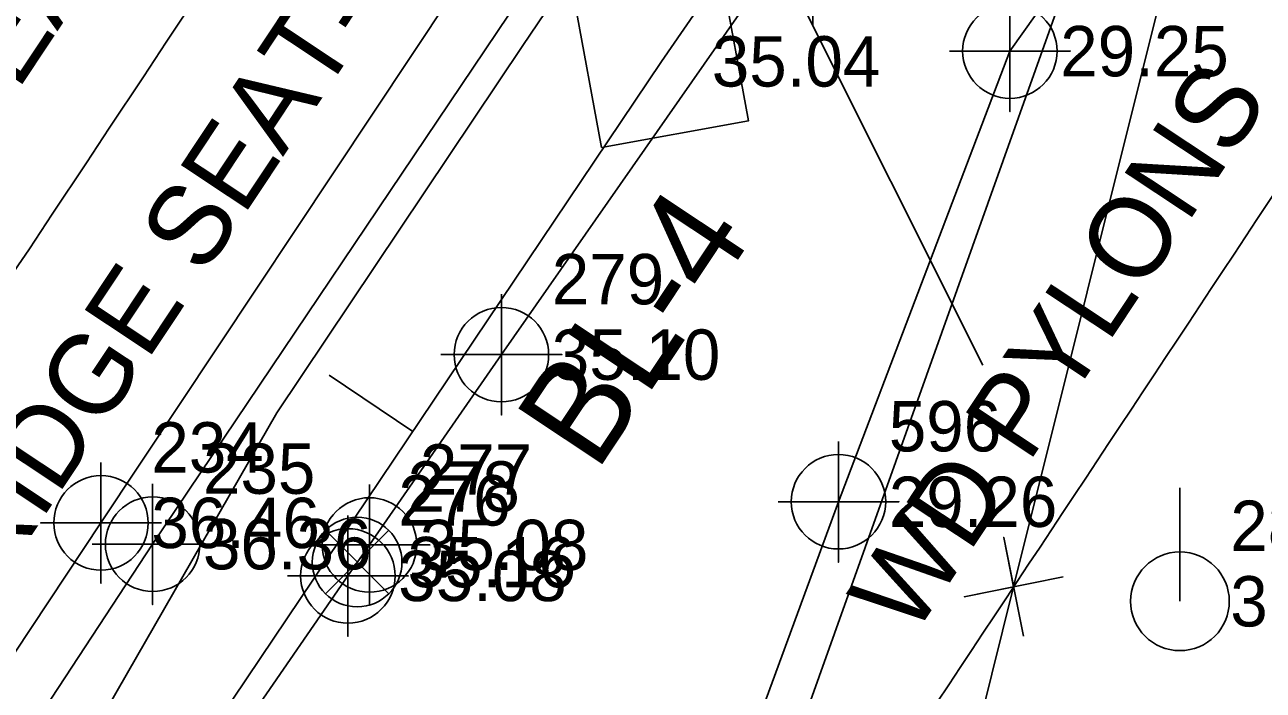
# Model space of a CAD drawing. Extents: x 2603627 to 2605187, y 896619 to 899063.
# Drawn here: x 2604513.4 to 2604574.8, y 898093.2 to 898126.3 of the extents above; entities that cross this region are included whole.
import ezdxf

# ---------------------------------------------------------------- set-up
doc = ezdxf.new("R2010")
doc.units = 0
for name, color, linetype in [('CTL Supplemental Horizontal and Vertical CELL', 7, 'Continuous'), ('CTL Supplemental Horizontal and Vertical Cogo Elevation', 7, 'Continuous'), ('CTL Supplemental Horizontal and Vertical Text', 7, 'Continuous'), ('Exist DTM Drainline Cogo Elevation', 7, 'Continuous'), ('Exist DTM Drainline Cogo Number', 7, 'Continuous'), ('Exist DTM Drainline Cogo Point CELL', 7, 'Continuous'), ('Exist Guardrail', 7, 'Continuous'), ('Exist Horizontal Alignment', 7, 'Continuous'), ('Exist Horizontal Baseline Alignment', 7, 'Continuous'), ('Exist Horizontal Baseline Alignment Tick small', 7, 'Continuous'), ('Exist Hydro Jurisdictional Stream or Body of Water', 7, 'Continuous'), ('Exist Hydro Stream or Body of Water', 7, 'Continuous'), ('Exist Other Culture Located Object Leader', 7, 'Continuous'), ('Exist Other Culture Located Object Text', 7, 'Continuous'), ('Exist Property Corner CELL', 7, 'Continuous'), ('Exist Property Line', 7, 'Continuous'), ('Exist Property Tie Line', 7, 'Continuous'), ('Exist Property Tie Line Leader', 7, 'Continuous'), ('Exist Right of Way Line', 7, 'Continuous'), ('Exist Roads EOP', 7, 'Continuous'), ('Exist Roads EOP Cogo Elevation', 7, 'Continuous'), ('Exist Roads EOP Cogo Number', 7, 'Continuous'), ('Exist Roads EOP Cogo Point CELL', 7, 'Continuous'), ('Exist Roads EOT', 7, 'Continuous'), ('Exist Roads EOT Cogo Elevation', 7, 'Continuous'), ('Exist Roads EOT Cogo Number', 7, 'Continuous'), ('Exist Roads EOT Cogo Point CELL', 7, 'Continuous'), ('Exist Structure Major Bridge Seat Top Elevation', 7, 'Continuous'), ('Exist Utilities Power Pole CELL', 7, 'Continuous'), ('Exist Utilities Power Pole Cogo Elevation', 7, 'Continuous'), ('Exist Utilities Power Pole Cogo Number', 7, 'Continuous'), ('Exist Utilities Water UG Line SUE LOS B', 7, 'Continuous'), ('Exist Utilities Water UG Line SUE LOS B Cogo Elevation', 7, 'Continuous'), ('Exist Utilities Water UG Line SUE LOS B Cogo Number', 7, 'Continuous'), ('Exist Utilities Water UG Line SUE LOS B Cogo Point CELL', 7, 'Continuous'), ('Exist Utilities Water Valve CELL', 7, 'Continuous'), ('Exist Utilities Water Valve Cogo Elevation', 7, 'Continuous'), ('Exist Utilities Water Valve Cogo Number', 7, 'Continuous')]:
    doc.layers.add(name, color=color, linetype=linetype)

# ---------------------------------------------------------------- blocks, each defined once
blk = doc.blocks.new('EXIST ROADS EOT COGO POINT')
at = {"layer": 'Exist Roads EOT Cogo Point CELL'}
blk.add_lwpolyline([(0, 0.06), (0, -0.06), (0, 0), (-0.06, 0), (0.06, 0)], dxfattribs=at)
blk.add_circle((0, 0), 0.0469, dxfattribs=at)
blk = doc.blocks.new('EXIST ROADS EOP COGO POINT')
at = {"layer": 'Exist Roads EOP Cogo Point CELL'}
blk.add_lwpolyline([(0, 0.06), (0, -0.06), (0, 0), (0.06, 0), (-0.06, 0)], dxfattribs=at)
blk.add_circle((0, 0), 0.0469, dxfattribs=at)
blk = doc.blocks.new('EXIST UTILITIES WATER UG LINE SUE LOS B COGO POINT')
at = {"layer": 'Exist Utilities Water UG Line SUE LOS B Cogo Point CELL'}
blk.add_lwpolyline([(0, 0.06), (0, -0.06), (0, 0), (0.06, 0), (-0.06, 0)], dxfattribs=at)
blk.add_circle((0, 0), 0.0469, dxfattribs=at)
blk = doc.blocks.new('EXIST UTILITIES WATER VALVE')
at = {"layer": 'Exist Utilities Water Valve CELL'}
blk.add_lwpolyline([(0.0315, 0.0315), (-0.0315, -0.0315), (0, 0), (0.0315, -0.0315), (-0.0315, 0.0315)], dxfattribs=at)
blk.add_circle((0, 0), 0.0445, dxfattribs=at)
blk = doc.blocks.new('EXIST DTM DRAINLINE COGO POINT')
at = {"layer": 'Exist DTM Drainline Cogo Point CELL'}
blk.add_lwpolyline([(0, 0.06), (0, -0.06), (0, 0), (0.06, 0), (-0.06, 0)], dxfattribs=at)
blk.add_circle((0, 0), 0.0469, dxfattribs=at)
blk = doc.blocks.new('CTL SUPPLEMENTAL HORIZONTAL AND VERTICAL')
at = {"layer": 'CTL Supplemental Horizontal and Vertical CELL'}
blk.add_line((0, 0), (0, 0), dxfattribs=at)
blk.add_lwpolyline([(-0.1043, 0.0004), (0.0005, 0.1052), (0.1055, 0.0002), (0.0007, -0.1047)], close=True, dxfattribs=at)

msp = doc.modelspace()

# ---------------------------------------------------------------- linework, layer by layer
at = {"layer": 'Exist Guardrail'}
msp.add_lwpolyline([(2604547.116, 898138.593), (2604538.083, 898125.227), (2604525.862, 898106.986), (2604516.084, 898089.953)], dxfattribs=at)
at = {"layer": 'Exist Horizontal Alignment'}
msp.add_arc((2574512.676, 918013.514), 36000, 326.4094331, 326.5137949, dxfattribs=at)
at = {"layer": 'Exist Horizontal Baseline Alignment'}
for p, q in [((2604544.961, 898124.436), (2604793.601, 898483.903)), ((2604301.74, 897762.526), (2604544.961, 898124.436))]:
    msp.add_line(p, q, dxfattribs=at)
at = {"layer": 'Exist Horizontal Baseline Alignment Tick small'}
msp.add_line((2604532.613, 898106.063), (2604528.463, 898108.852), dxfattribs=at)
at = {"layer": 'Exist Hydro Jurisdictional Stream or Body of Water'}
msp.add_lwpolyline([(2604496.633, 897894.568), (2604506.622, 897939.052), (2604520.359, 897991.754), (2604531.2, 898032.054), (2604542.791, 898072.726), (2604553.749, 898102.573), (2604562.259, 898124.945)], dxfattribs=at)
at = {"layer": 'Exist Hydro Stream or Body of Water'}
msp.add_line((2604562.259, 898124.945), (2604566.71, 898131.232), dxfattribs=at)
at = {"layer": 'Exist Other Culture Located Object Leader'}
for p, q in [((2604552.474, 898136.112), (2604552.474, 898126.227)), ((2604549.749, 898131.676), (2604560.915, 898109.347))]:
    msp.add_line(p, q, dxfattribs=at)
at = {"layer": 'Exist Property Corner CELL'}
msp.add_line((2604562.447, 898098.35), (2604562.447, 898098.35), dxfattribs=at)
msp.add_lwpolyline([(2604562.941, 898095.9), (2604561.952, 898100.801), (2604562.447, 898098.35), (2604559.996, 898097.856), (2604564.898, 898098.845)], dxfattribs=at)
at = {"layer": 'Exist Property Line'}
msp.add_line((2604562.447, 898098.35), (2604410.231, 897487.876), dxfattribs=at)
at = {"layer": 'Exist Property Tie Line'}
msp.add_line((2604598.893, 898244.519), (2604562.447, 898098.35), dxfattribs=at)
at = {"layer": 'Exist Property Tie Line Leader'}
msp.add_lwpolyline([(2604573.79, 898143.82), (2604569.62, 898141.109), (2604502.964, 897954.217), (2604488.283, 897929.59)], dxfattribs=at)
at = {"layer": 'Exist Right of Way Line'}
msp.add_arc((2574512.676, 918013.514), 36050, 326.4094331, 326.5137949, dxfattribs=at)
at = {"layer": 'Exist Roads EOP'}
msp.add_line((2604519.702, 898100.467), (2604548.851, 898143.803), dxfattribs=at)
msp.add_lwpolyline([(2604057.72, 897404.053), (2604078.217, 897434.825), (2604108.356, 897480.055), (2604137.928, 897524.858), (2604167.354, 897568.955), (2604196.06, 897612.167), (2604224.865, 897655.677), (2604253.509, 897698.95), (2604283.958, 897744.636), (2604314.741, 897791.034), (2604343.965, 897835.342), (2604373.308, 897879.599), (2604402.104, 897923.177), (2604431.636, 897967.591), (2604461.241, 898012.022), (2604491.049, 898056.884), (2604519.702, 898100.467)], dxfattribs=at)
at = {"layer": 'Exist Roads EOT'}
msp.add_line((2604517.139, 898101.524), (2604546.328, 898145.455), dxfattribs=at)
msp.add_lwpolyline([(2604055.127, 897405.772), (2604075.391, 897436.304), (2604105.721, 897481.843), (2604135.414, 897526.582), (2604164.512, 897570.475), (2604193.141, 897613.838), (2604222.022, 897657.584), (2604250.729, 897700.626), (2604281.078, 897746.073), (2604311.9, 897792.558), (2604341.367, 897836.941), (2604370.816, 897881.236), (2604399.644, 897924.707), (2604429.03, 897968.884), (2604458.854, 898013.95), (2604488.435, 898058.326), (2604517.139, 898101.524)], dxfattribs=at)
at = {"layer": 'Exist Utilities Power Pole CELL'}
for q in [(2604570.701, 898103.257), (2604570.701, 898097.632)]:
    msp.add_line((2604570.701, 898097.632), q, dxfattribs=at)
msp.add_circle((2604570.701, 898097.632), 2.45, dxfattribs=at)
at = {"layer": 'Exist Utilities Water UG Line SUE LOS B'}
msp.add_lwpolyline([(2604076.502, 897391.6), (2604089.191, 897412.441), (2604108.022, 897444.81), (2604130.464, 897486.167), (2604138.607, 897502.499), (2604141.743, 897510.424), (2604157.294, 897542.112), (2604195.613, 897598.858), (2604232.991, 897655.201), (2604269.717, 897709.187), (2604303.431, 897758.706), (2604343.238, 897819.021), (2604371.6, 897861.277), (2604402.524, 897906.632), (2604434.42, 897955.25), (2604460.628, 897996.692), (2604477.786, 898022.594), (2604502.249, 898059.637), (2604529.396, 898098.892), (2604530.468, 898100.429), (2604537.018, 898109.876), (2604550.547, 898129.275)], dxfattribs=at)

# ---------------------------------------------------------------- block references
at = {"layer": 'CTL Supplemental Horizontal and Vertical CELL', "xscale": 49.99999999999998, "yscale": 49.99999999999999, "rotation": 55.39369554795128}
msp.add_blockref('CTL SUPPLEMENTAL HORIZONTAL AND VERTICAL', (2604544.961, 898124.436), dxfattribs=at)
at = {"layer": 'Exist DTM Drainline Cogo Point CELL', "xscale": 50, "yscale": 50}
for p in [(2604562.259, 898124.945), (2604553.749, 898102.573)]:
    msp.add_blockref('EXIST DTM DRAINLINE COGO POINT', p, dxfattribs=at)
at = {"layer": 'Exist Roads EOP Cogo Point CELL', "xscale": 50, "yscale": 50}
msp.add_blockref('EXIST ROADS EOP COGO POINT', (2604519.702, 898100.467), dxfattribs=at)
at = {"layer": 'Exist Roads EOT Cogo Point CELL', "xscale": 50, "yscale": 50}
msp.add_blockref('EXIST ROADS EOT COGO POINT', (2604517.139, 898101.524), dxfattribs=at)
at = {"layer": 'Exist Utilities Water UG Line SUE LOS B Cogo Point CELL', "xscale": 50, "yscale": 50}
for p in [(2604537.018, 898109.876), (2604530.468, 898100.429), (2604529.396, 898098.892)]:
    msp.add_blockref('EXIST UTILITIES WATER UG LINE SUE LOS B COGO POINT', p, dxfattribs=at)
at = {"layer": 'Exist Utilities Water Valve CELL', "xscale": 50, "yscale": 50}
msp.add_blockref('EXIST UTILITIES WATER VALVE', (2604529.855, 898099.58), dxfattribs=at)

# ---------------------------------------------------------------- texts
at = {"layer": 'CTL Supplemental Horizontal and Vertical Cogo Elevation'}
msp.add_text('35.04', height=2.5, dxfattribs=at).set_placement((2604547.461, 898123.186))
at = {"layer": 'CTL Supplemental Horizontal and Vertical Text'}
msp.add_text('BL-4', height=5, rotation=56.40943, dxfattribs=at).set_placement((2604541.722, 898103.983))
at = {"layer": 'Exist DTM Drainline Cogo Elevation'}
for s, p in [('29.25', (2604564.759, 898123.695)), ('29.26', (2604556.249, 898101.323))]:
    msp.add_text(s, height=2.5, dxfattribs=at).set_placement(p)
at = {"layer": 'Exist DTM Drainline Cogo Number'}
msp.add_text('596', height=2.5, dxfattribs=at).set_placement((2604556.249, 898105.073))
at = {"layer": 'Exist Other Culture Located Object Text'}
msp.add_text('WD PYLONS', height=4, rotation=56.47848, dxfattribs=at).set_placement((2604557.435, 898095.773))
at = {"layer": 'Exist Roads EOP Cogo Elevation'}
msp.add_text('36.36', height=2.5, dxfattribs=at).set_placement((2604522.202, 898099.217))
at = {"layer": 'Exist Roads EOP Cogo Number'}
msp.add_text('235', height=2.5, dxfattribs=at).set_placement((2604522.202, 898102.967))
at = {"layer": 'Exist Roads EOT Cogo Elevation'}
msp.add_text('36.46', height=2.5, dxfattribs=at).set_placement((2604519.639, 898100.274))
at = {"layer": 'Exist Roads EOT Cogo Number'}
msp.add_text('234', height=2.5, dxfattribs=at).set_placement((2604519.639, 898104.024))
at = {"layer": 'Exist Structure Major Bridge Seat Top Elevation'}
for s, p in [("BRIDGE SEAT=33.05'", (2604498.852, 898101.651)), ("BRIDGE SEAT=33.04'", (2604510.053, 898095.415))]:
    msp.add_text(s, height=4, rotation=56.40944, dxfattribs=at).set_placement(p)
at = {"layer": 'Exist Utilities Power Pole Cogo Elevation'}
msp.add_text('31.91', height=2.5, dxfattribs=at).set_placement((2604573.201, 898096.382))
at = {"layer": 'Exist Utilities Power Pole Cogo Number'}
msp.add_text('281', height=2.5, dxfattribs=at).set_placement((2604573.201, 898100.132))
at = {"layer": 'Exist Utilities Water UG Line SUE LOS B Cogo Elevation'}
for s, p in [('35.10', (2604539.518, 898108.626)), ('35.08', (2604532.968, 898099.179)), ('35.08', (2604531.896, 898097.642))]:
    msp.add_text(s, height=2.5, dxfattribs=at).set_placement(p)
at = {"layer": 'Exist Utilities Water UG Line SUE LOS B Cogo Number'}
for s, p in [('279', (2604539.518, 898112.376)), ('277', (2604532.968, 898102.929)), ('276', (2604531.896, 898101.392))]:
    msp.add_text(s, height=2.5, dxfattribs=at).set_placement(p)
at = {"layer": 'Exist Utilities Water Valve Cogo Elevation'}
msp.add_text('35.16', height=2.5, dxfattribs=at).set_placement((2604532.355, 898098.33))
at = {"layer": 'Exist Utilities Water Valve Cogo Number'}
msp.add_text('278', height=2.5, dxfattribs=at).set_placement((2604532.355, 898102.08))

doc.saveas('drawing.dxf')
